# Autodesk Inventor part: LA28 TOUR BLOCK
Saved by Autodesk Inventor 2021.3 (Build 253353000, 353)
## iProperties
Created: 2023-01
Part Number: LA28 TOUR BLOCK
Material: Generic
Document SubType Name: Modeling
Designer: AdminForWorker
Density: 1 g/cm^3
Appearance: Default
Title: LA28 TOUR BLOCK v2
Author: AdminForWorker
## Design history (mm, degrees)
fillet "Fillet3"
body "Solid1"
